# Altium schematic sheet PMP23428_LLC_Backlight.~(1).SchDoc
size 431 x 279 mm; Date: Not shown in title block; ApprovedBy: Not shown in title block; CheckedBy: Not shown in title block; Author: Not shown in title block; CompanyName: Not shown in title block; Engineer: Not shown in title block; Organization: Not shown in title block; Address1: Not shown in title block; Address2: Not shown in title block; Address3: Not shown in title block; Address4: Not shown in title block; DocumentNumber: 2; Revision: Use project parameter SCH_Rev; SheetNumber: 2; SheetTotal: 3; PageSetup: Record=PageOptions¦CenterHorizontal=True¦CenterVertical=True¦PrintScale=1.00¦XCorrection=1.00¦YCorrection=1.00¦PrintKind=0¦BorderSize=5000000¦LeftOffset=0¦BottomOffset=0¦Orientation=2¦PaperLength=1000¦PaperWidth=1000¦Scale=100¦PaperSource=15¦PrintQuality=600¦MediaType=1¦DitherType=10¦PaperKind=Letter¦PrintScaleMode=1
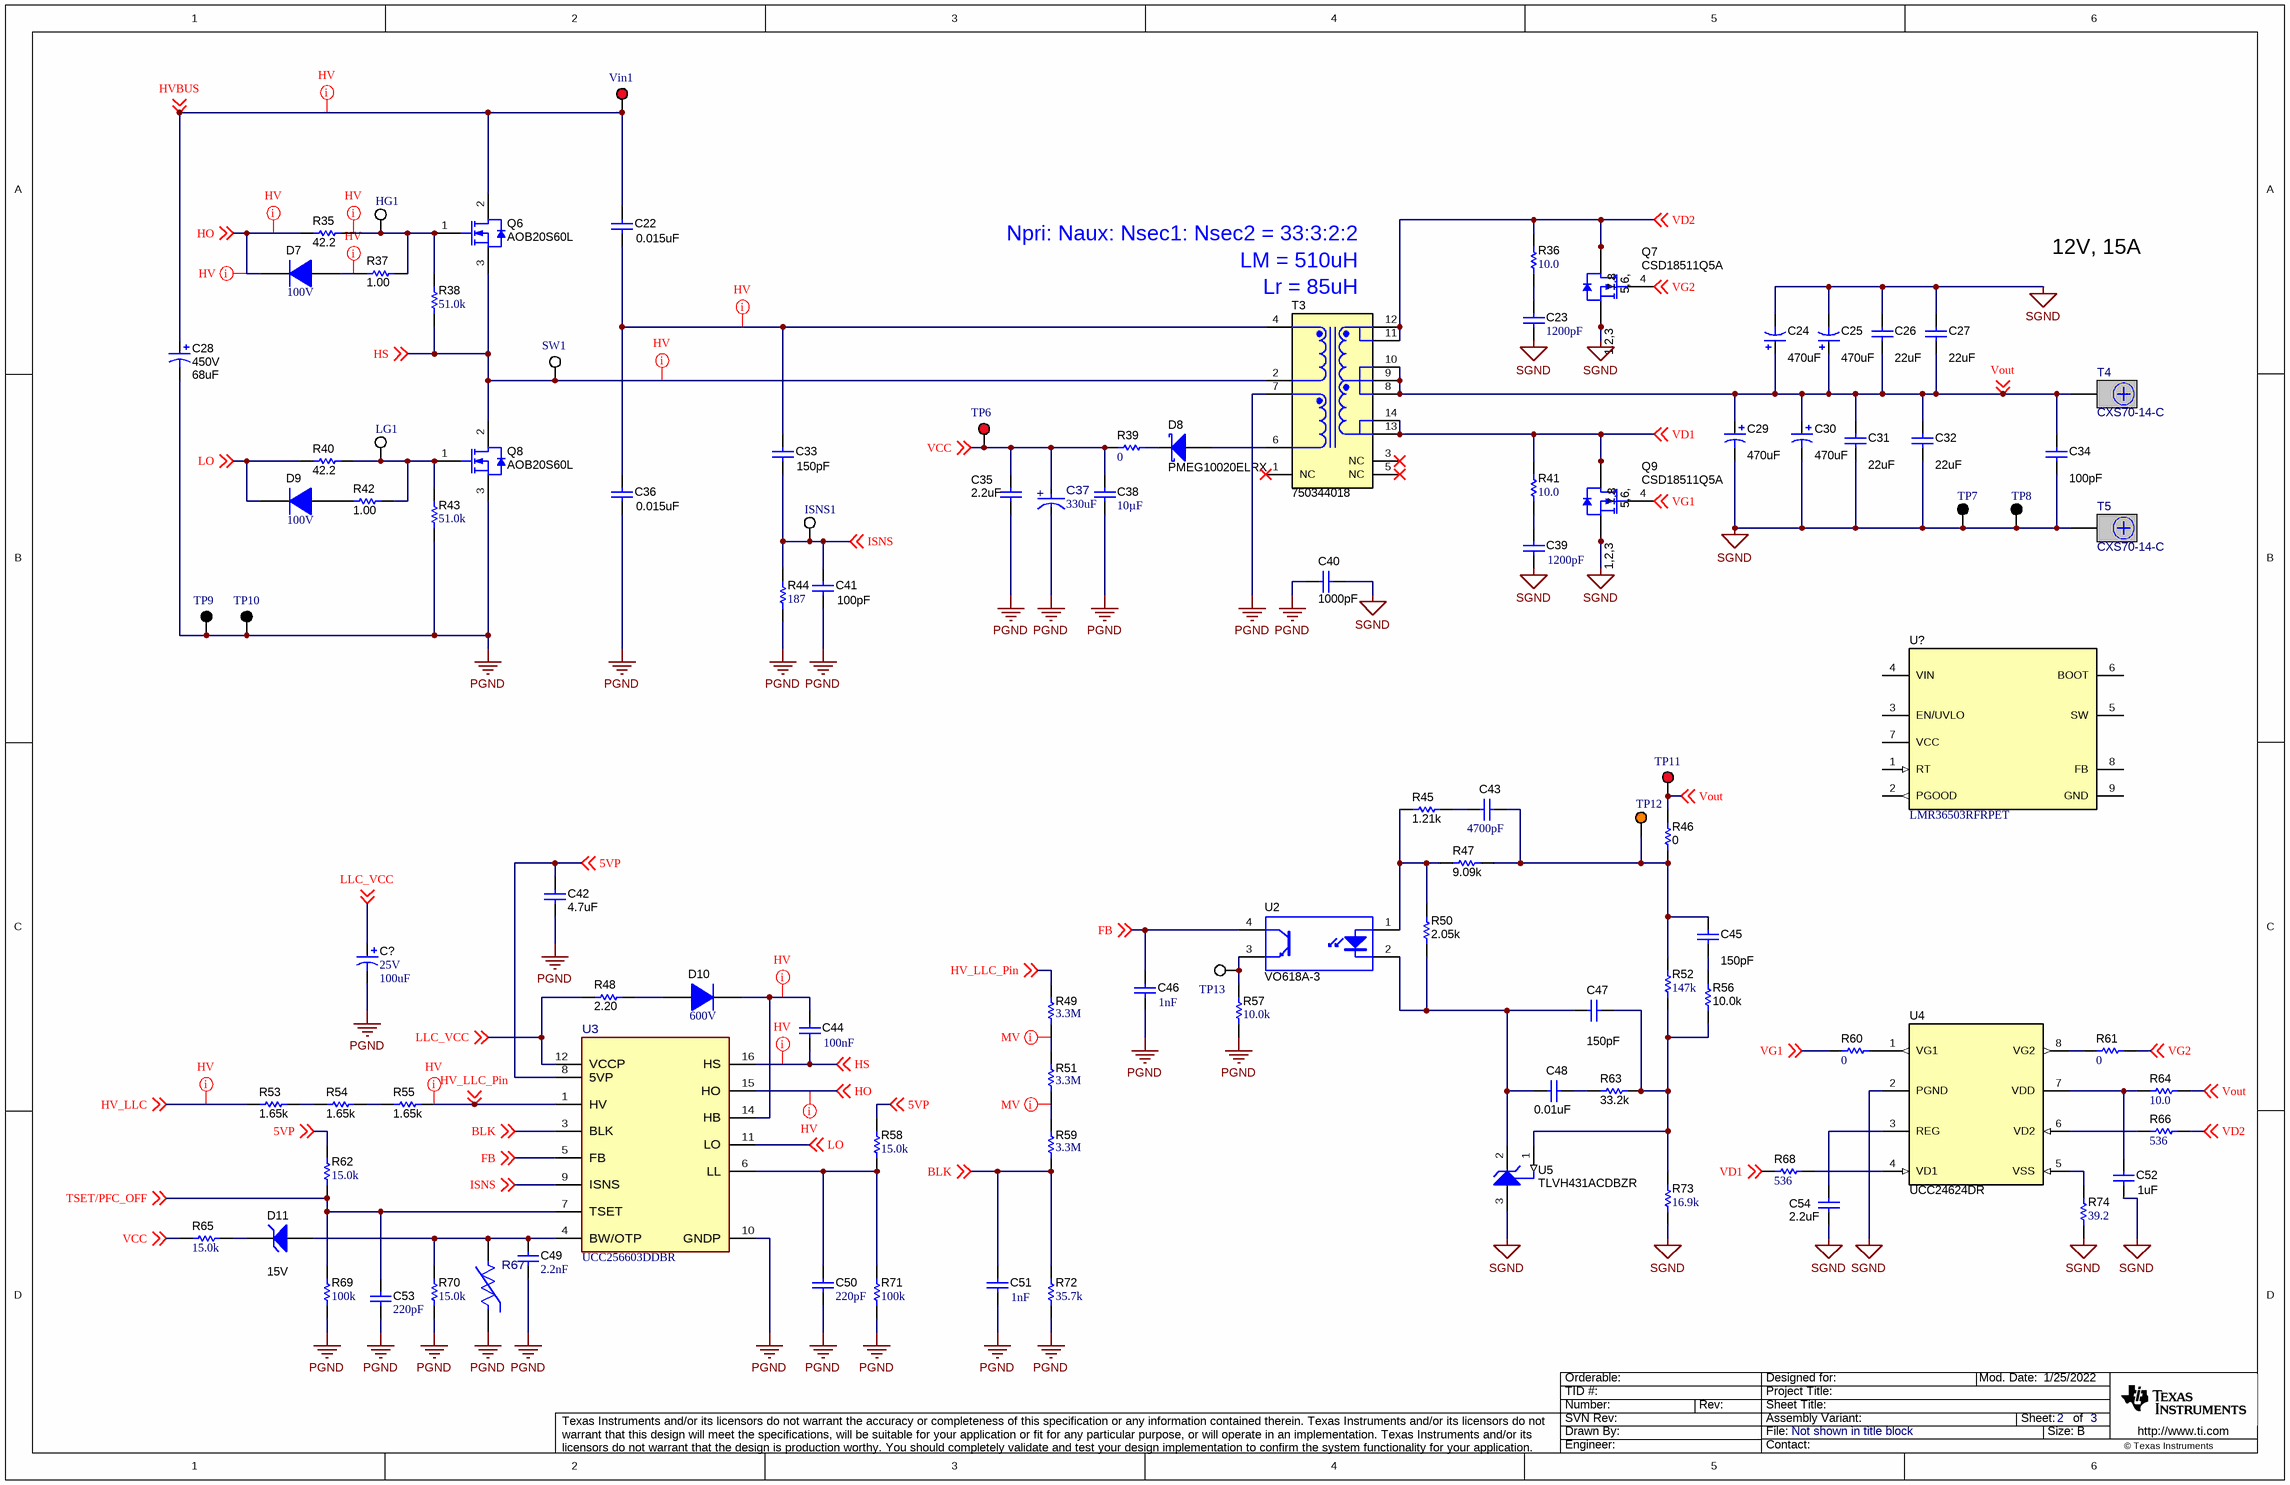
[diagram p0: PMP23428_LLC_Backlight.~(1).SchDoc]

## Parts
C22  ValueDisplayed: 0.015uF  [B32652_1800x700x1250]  (hidden comment: B32652A7153J000)
C23  ValueDisplayed: 1200pF  [0805L]  (hidden comment: GRM2165C2A122JA01D)
C24  ValueDisplayed: 470uF  [HW_1000x1600]  (hidden comment: UHW1V471MPD)
C25  ValueDisplayed: 470uF  [HW_1000x1600]  (hidden comment: UHW1V471MPD)
C26  ValueDisplayed: 22uF  [1206_190L]  (hidden comment: C3216X5R1E226M160AB)
C27  ValueDisplayed: 22uF  [1206_190L]  (hidden comment: C3216X5R1E226M160AB)
C28  VDC_V: 450V  ValueDisplayed: 68uF  [KXG_1800x3150]  (hidden comment: EKXG451ELL680MMN3S)
C29  ValueDisplayed: 470uF  [HW_1000x1600]  (hidden comment: UHW1V471MPD)
C30  ValueDisplayed: 470uF  [HW_1000x1600]  (hidden comment: UHW1V471MPD)
C31  ValueDisplayed: 22uF  [1206_190L]  (hidden comment: C3216X5R1E226M160AB)
C32  ValueDisplayed: 22uF  [1206_190L]  (hidden comment: C3216X5R1E226M160AB)
C33  ValueDisplayed: 150pF  [1206L]  (hidden comment: GRM31A5C2J151JW01D)
C34  ValueDisplayed: 100pF  [0603L]  (hidden comment: 06035A101FAT2A)
C35  ValueDisplayed: 2.2uF  [0805L]  (hidden comment: C2012X7R1V225K085AC)
C36  ValueDisplayed: 0.015uF  [B32652_1800x700x1250]  (hidden comment: B32652A7153J000)
C37  ValueDisplayed: 330uF  [FP-35ZL330MEFC10X16_RADIAL-MFG]  (hidden comment: 35ZL330MEFC10X16)
C38  ValueDisplayed: 10µF  [1206_180]  (hidden comment: C1206C106J3RACAUTO)
C39  ValueDisplayed: 1200pF  [0805L]  (hidden comment: GRM2165C2A122JA01D)
C40  ValueDisplayed: 1000pF  [CD45_700x600x1100]  (hidden comment: CD45-E2GA102M-NKA)
C41  ValueDisplayed: 100pF  [1206L]  (hidden comment: 12061A101JAT2A)
C42  ValueDisplayed: 4.7uF  [1206L]  (hidden comment: C3216X7R1E475K085AB)
C43  ValueDisplayed: 4700pF  [0603L]  (hidden comment: C0603C472J1GAC7867)
C44  Cap_F: 100nF  [1206_180L]  (hidden comment: GRM31C5C1E104JA01L)
C45  ValueDisplayed: 150pF  [0402L]  (hidden comment: 885012005062)
C46  Cap_F: 1nF  [1206L]  (hidden comment: 12061A102JAT2A)
C47  ValueDisplayed: 150pF  [0402L]  (hidden comment: 885012005062)
C48  ValueDisplayed: 0.01uF  [0603L]  (hidden comment: 06031C103JAT2A)
C49  Cap_F: 2.2nF  [0603]  (hidden comment: C0603X222K5RACTU)
C50  Cap_F: 220pF  [0603]  (hidden comment: C0603X221K5RACTU)
C51  Cap_F: 1nF  [0402L]  (hidden comment: 04025C102JAT2A)
C52  ValueDisplayed: 1uF  [0603L]  (hidden comment: GRM188R71C105KE15D)
C53  Cap_F: 220pF  [0603]  (hidden comment: C0603X221K5RACTU)
C54  ValueDisplayed: 2.2uF  [0805L]  (hidden comment: C2012X7R1V225K085AC)
C?  VDC_V: 25V  ValueDisplayed: 100uF  [SM_RADIAL_E]  (hidden comment: EEE-FK1E101P)
D7  Vr_V: 100V  [SOD-123]  (hidden comment: 1N4148W-7-F)
D8  PMEG10020ELRX  [SOD-123W]
D9  Vr_V: 100V  [SOD-123]  (hidden comment: 1N4148W-7-F)
D10  Vr_V: 600V  [SMAF]  (hidden comment: ES1JAF)
D11  value 15V  [SOD-123]  (hidden comment: DDZ15-7)
HG1  5012  [Keystone5012]  (value not drawn)
ISNS1  5012  [Keystone5012]  (value not drawn)
LG1  5012  [Keystone5012]  (value not drawn)
Q6  AOB20S60L  [DDPAK]
Q7  CSD18511Q5A  [DQJ0008A]
Q8  AOB20S60L  [DDPAK]
Q9  CSD18511Q5A  [DQJ0008A]
R35  ValueDisplayed: 42.2  [0603]  (hidden comment: RC0603FR-0742R2L)
R36  ValueDisplayed: 10.0  [1206L]  (hidden comment: RC1206FR-0710RL)
R37  ValueDisplayed: 1.00  [0603L]  (hidden comment: RC0603FR-071RL)
R38  ValueDisplayed: 51.0k  [0603L]  (hidden comment: RC0603FR-0751KL)
R39  ValueDisplayed: 0  [1206L]  (hidden comment: ERJ-8GEY0R00V)
R40  ValueDisplayed: 42.2  [0603L]  (hidden comment: RC0603FR-0742R2L)
R41  ValueDisplayed: 10.0  [1206L]  (hidden comment: RC1206FR-0710RL)
R42  ValueDisplayed: 1.00  [0603L]  (hidden comment: RC0603FR-071RL)
R43  ValueDisplayed: 51.0k  [0603L]  (hidden comment: RC0603FR-0751KL)
R44  ValueDisplayed: 187  [1206]  (hidden comment: RC1206FR-07187RL)
R45  ValueDisplayed: 1.21k  [0603L]  (hidden comment: RC0603FR-071K21L)
R46  ValueDisplayed: 0  [0402L]  (hidden comment: RC0402JR-070RL)
R47  ValueDisplayed: 9.09k  [0603L]  (hidden comment: RC0603FR-079K09L)
R48  ValueDisplayed: 2.20  [0603L]  (hidden comment: ERJ-3RQF2R2V)
R49  Res_ohm: 3.3M  [FP-KTR18EZPF3304_1206-MFG]  (hidden comment: KTR18EZPF3304)
R50  ValueDisplayed: 2.05k  [0603L]  (hidden comment: RC0603FR-072K05L)
R51  Res_ohm: 3.3M  [FP-KTR18EZPF3304_1206-MFG]  (hidden comment: KTR18EZPF3304)
R52  ValueDisplayed: 147k  [0603L]  (hidden comment: RC0603FR-07147KL)
R53  ValueDisplayed: 1.65k  [1206L]  (hidden comment: CRCW12061K65FKEA)
R54  ValueDisplayed: 1.65k  [1206L]  (hidden comment: CRCW12061K65FKEA)
R55  ValueDisplayed: 1.65k  [1206L]  (hidden comment: CRCW12061K65FKEA)
R56  ValueDisplayed: 10.0k  [0603L]  (hidden comment: ERJ-3EKF1002V)
R57  ValueDisplayed: 10.0k  [0402L]  (hidden comment: ERJ-2RKF1002X)
R58  ValueDisplayed: 15.0k  [0603]  (hidden comment: RT0603BRD0715KL)
R59  Res_ohm: 3.3M  [FP-KTR18EZPF3304_1206-MFG]  (hidden comment: KTR18EZPF3304)
R60  ValueDisplayed: 0  [0603L]  (hidden comment: RC0603JR-070RL)
R61  ValueDisplayed: 0  [0603L]  (hidden comment: RC0603JR-070RL)
R62  ValueDisplayed: 15.0k  [0603]  (hidden comment: RT0603BRD0715KL)
R63  ValueDisplayed: 33.2k  [0603L]  (hidden comment: RC0603FR-0733K2L)
R64  ValueDisplayed: 10.0  [0603L]  (hidden comment: RC0603FR-0710RL)
R65  ValueDisplayed: 15.0k  [0603]  (hidden comment: RG1608P-153-B-T5)
R66  ValueDisplayed: 536  [0603L]  (hidden comment: RT0603BRD07536RL)
R67  B57371V2474J060  [FP-B57371V2474J060_0603-MFG]  (value not drawn)
R68  ValueDisplayed: 536  [0603L]  (hidden comment: RT0603BRD07536RL)
R69  ValueDisplayed: 100k  [0603]  (hidden comment: RT0603BRD07100KL)
R70  ValueDisplayed: 15.0k  [0603]  (hidden comment: RG1608P-153-B-T5)
R71  ValueDisplayed: 100k  [0603]  (hidden comment: RT0603BRD07100KL)
R72  ValueDisplayed: 35.7k  [0603]  (hidden comment: RT0603BRD0735K7L)
R73  ValueDisplayed: 16.9k  [0603L]  (hidden comment: RC0603FR-0716K9L)
R74  ValueDisplayed: 39.2  [0603L]  (hidden comment: RC0603FR-0739R2L)
SW1  5012  [Keystone5012]  (value not drawn)
T3  750344018  [Wurth_750344018]
T4  CXS70-14-C  [Panduit_CXS70-14-C]
T5  CXS70-14-C  [Panduit_CXS70-14-C]
TP6  5010  [Keystone5010]  (value not drawn)
TP7  5011  [Keystone5011]  (value not drawn)
TP8  5011  [Keystone5011]  (value not drawn)
TP9  5011  [Keystone5011]  (value not drawn)
TP10  5011  [Keystone5011]  (value not drawn)
TP11  5010  [Keystone5010]  (value not drawn)
TP12  5013  [Keystone5013]  (value not drawn)
TP13  5012  [Keystone5012]  (value not drawn)
U2  VO618A-3  [DIP-4]
U3  UCC256603DDBR  [DDB0014A-MFG]
U4  UCC24624DR  [D0008A_N]
U5  TLVH431ACDBZR  [DBZ0003A_N]
U?  LMR36503RFRPET  [RPE0009A]
Vin1  5010  [Keystone5010]  (value not drawn)

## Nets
PGND: C28.2(-) C35.2 C36.2 C37.1(CATHODE) C38.2 C40.2 C41.2 C42.2 C46.2 C49.2 C50.2 C51.2 C53.2 C?.2(-) Q8.3(S) R43.1 R44.1 R57.1 R67.1 R69.1 R70.1 R71.1 R72.1 T3.7 TP9.1 TP10.1 U3.10(GNDP)
SGND: C23.2 C24.2(-) C25.2(-) C26.1 C27.1 C29.2(-) C30.2(-) C31.2 C32.2 C34.2 C39.2 C40.1 C52.2 C54.2 Q7.1(S) Q7.2(S) Q7.3(S) Q9.1(S) Q9.2(S) Q9.3(S) R73.1 R74.2 T5.1 TP7.1 TP8.1 U4.2(PGND) U5.3(ANODE)
5VP: C42.1 R58.2 R62.2 U3.8(5VP) ; off-sheet 5VP
BLK: C51.1 R59.1 R72.2 U3.3(BLK) ; off-sheet BLK
FB: C46.1 U2.4(C) U3.5(FB) ; off-sheet FB
HO: D7.1(K) R35.1 U3.15(HO) ; off-sheet HO
HS: C44.2 Q6.3(S) Q8.2(D) R38.1 SW1.1 T3.2 U3.16(HS) ; off-sheet HS
HV_LLC: R53.1 ; off-sheet HV_LLC
HV_LLC_Pin: R49.2 R55.2 U3.1(HV) ; off-sheet HV_LLC_Pin
HVBUS: C22.1 C28.1(+) Q6.2(D) Vin1.1 ; off-sheet HVBUS
ISNS: C33.2 C41.1 ISNS1.1 R44.2 U3.9(ISNS) ; off-sheet ISNS
LLC_VCC: C?.1(+) R48.1 U3.12(VCCP) ; off-sheet LLC_VCC
LO: D9.1(K) R40.1 U3.11(LO) ; off-sheet LO
TSET/PFC_OFF: C53.1 R62.1 R69.2 U3.7(TSET) ; off-sheet TSET/PFC_OFF
VCC: C35.1 C37.2(ANODE) C38.1 R39.1 R65.2 TP6.1 ; off-sheet VCC
VD1: Q9.5(D) Q9.6(D) Q9.7(D) Q9.8(D) Q9.9(D) R41.2 R68.2 T3.13 T3.14 ; off-sheet VD1
VD2: Q7.5(D) Q7.6(D) Q7.7(D) Q7.8(D) Q7.9(D) R36.2 R66.1 T3.11 T3.12 ; off-sheet VD2
VG1: Q9.4(G) R60.1 ; off-sheet VG1
VG2: Q7.4(G) R61.2 ; off-sheet VG2
Vout: C24.1(+) C25.1(+) C26.2 C27.2 C29.1(+) C30.1(+) C31.1 C32.1 C34.1 R46.2 R64.2 T3.8 T3.9 T3.10 T4.1 TP11.1 ; off-sheet Vout
NetC22_2: C22.2 C33.1 C36.1 T3.4
NetC23_1: C23.1 R36.1
NetC39_1: C39.1 R41.1
NetC43_1: C43.1 C45.1 R46.1 R47.2 R52.2 TP12.1
NetC43_2: C43.2 R45.2
NetC44_1: C44.1 D10.1(K) U3.14(HB)
NetC45_2: C45.2 R56.2
NetC47_1: C47.1 R52.1 R56.1 R63.1 R73.2 U5.1(REF)
NetC47_2: C47.2 C48.2 R50.1 U2.2(K) U5.2(CATHODE)
NetC48_1: C48.1 R63.2
NetC49_1: C49.1 D11.2(A) R67.2 R70.2 U3.4(BW/OTP)
NetC50_1: C50.1 R58.1 R71.2 U3.6(LL)
NetC52_1: C52.1 R64.1 U4.7(VDD)
NetC54_1: C54.1 U4.3(REG)
NetD7_2: D7.2(A) R37.1
NetD8_1: D8.1(K) R39.2
NetD8_2: D8.2(A) T3.6
NetD9_2: D9.2(A) R42.1
NetD10_2: D10.2(A) R48.2
NetD11_1: D11.1(K) R65.1
NetHG1_1: HG1.1 Q6.1(G) R35.2 R37.2 R38.2
NetLG1_1: LG1.1 Q8.1(G) R40.2 R42.2 R43.2
NetR45_1: R45.1 R47.1 R50.2 U2.1(A)
NetR49_1: R49.1 R51.2
NetR51_1: R51.1 R59.2
NetR53_2: R53.2 R54.1
NetR54_2: R54.2 R55.1
NetR57_2: R57.2 TP13.1 U2.3(E)
NetR60_2: R60.2 U4.1(VG1)
NetR61_1: R61.1 U4.8(VG2)
NetR66_2: R66.2 U4.6(VD2)
NetR68_1: R68.1 U4.4(VD1)
NetR74_1: R74.1 U4.5(VSS)

Not connected (* = marked no-connect by the designer): T3 1(NC)* 3(NC)* 5(NC)*; U? 1(RT) 2(PGOOD) 3(EN/UVLO) 4(VIN) 5(SW) 6(BOOT) 7(VCC) 8(FB) 9(GND)

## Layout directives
net class HV: HO, HS, HV_LLC, HV_LLC_Pin, HVBUS, NetC22_2, NetC44_1, NetD7_2, NetHG1_1
net class MV: NetR49_1, NetR51_1

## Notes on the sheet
- Npri: Naux: Nsec1: Nsec2 = 33:3:2:2
- LM = 510uH
- (near T3) Lr = 85uH
- 12V, 15A

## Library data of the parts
C22 C36 = CMP-0012346-3: CAP, Film, 0.015 uF, 1250 V, +/- 5%, AEC-Q200 Grade 3, TH; Manufacturer: TDK; TaMin_C: -55°C; Polarized: N; SizeAreaWB_mm2: 180; Value1: Unknown; TaMax_C: 100°C; SizeZ_mm: 12.5; SizeX_mm: 18; SizeY_mm: 7; Cap_Case: 18x7x12.5; Value2: 1250V; SizeArea_mm2: 126; CompType: Capacitor; AEC Qualified: Y; Cap_F: 15nF; VDC_V: 1.25kV; AEC Grade: 3; AEC Category: Q200
C23 C39 = CMP-0008098-2: CAP, CERM, 1200 pF, 100 V, +/- 5%, C0G/NP0, 0805; Manufacturer: MuRata; TaMin_C: -55°C; Polarized: N; SizeAreaWB_mm2: 6.75; Value1: Unknown; U/M: EA; Value: 1200pF; TaMax_C: 125°C; SizeZ_mm: 1.45; SizeX_mm: 2; SizeY_mm: 1.25; Cap_Case: 0805; Value2: 100V; SizeArea_mm2: 2.5; Cap_F: 1.2nF; AEC Category: Q200
C24 C25 C29 C30 = CMP-0010541-2: CAP, AL, 470 uF, 35 V, +/- 20%, 0.03 ohm, TH; Manufacturer: Nichicon; TaMin_C: -40°C; ESR_ohm: 0.03; Polarized: Y; SizeAreaWB_mm2: 144; U/M: EA; Value: 470uF; TaMax_C: 105°C; SizeZ_mm: 17.5; SizeX_mm: 10; Cap_Case: 10x16mm; Value2: 35V; SizeArea_mm2: 100; CompType: Capacitor; AEC Qualified: N; Cap_F: 470µF; IRMS_A: 2A; AEC Category: Q200
C26 C27 C31 C32 = CMP-0008654-2: CAP, CERM, 22 uF, 25 V, +/- 20%, X5R, 1206_190; Manufacturer: TDK; TaMin_C: -55°C; Polarized: N; SizeAreaWB_mm2: 10.92; Value1: Unknown; U/M: EA; Value: 22uF; TaMax_C: 85°C; SizeZ_mm: 1.9; SizeX_mm: 3.2; SizeY_mm: 1.6; Cap_Case: 1206; Value2: 25V; SizeArea_mm2: 5.12; CompType: Capacitor; Cap_F: 22µF; AEC Category: Q200
C28 = CMP-0010043-2: CAP, AL, 68 uF, 450 V, +/- 20%, TH; Manufacturer: Chemi-Con; TaMin_C: -25°C; Polarized: Y; SizeAreaWB_mm2: 400; Value1: Unknown; U/M: EA; Value: 68uF; TaMax_C: 105°C; SizeZ_mm: 33; SizeX_mm: 18; Cap_Case: 18x31.5mm; SizeArea_mm2: 324; CompType: Capacitor; Cap_F: 68µF; IRMS_A: 6.3dA; AEC Category: Q200
C33 = CMP-0008885-2: CAP, CERM, 150 pF, 630 V, +/- 5%, C0G/NP0, 1206; Manufacturer: MuRata; TaMin_C: -55°C; Polarized: N; SizeAreaWB_mm2: 10.92; Value1: Unknown; U/M: EA; Value: 150pF; TaMax_C: 125°C; SizeZ_mm: 1.35; SizeX_mm: 3.2; SizeY_mm: 1.6; Cap_Case: 1206; Value2: 630V; SizeArea_mm2: 5.12; CompType: Capacitor; AEC Category: Q200
C34 = CMP-0006762-4: CAP, CERM, 100 pF, 50 V, +/- 1%, C0G/NP0, 0603; Manufacturer: AVX; TaMin_C: -55°C; Polarized: N; SizeAreaWB_mm2: 4.68; Value1: Unknown; U/M: EA; TaMax_C: 125°C; SizeZ_mm: 1; SizeX_mm: 1.6; SizeY_mm: 0.8; Cap_Case: 0603; Value2: 50V; SizeArea_mm2: 1.28; CompType: Capacitor; Value: 100pF; AEC Category: Q200
C35 C54 = CMP-0007883-2: CAP, CERM, 2.2 uF, 35 V, +/- 10%, X7R, 0805; Manufacturer: TDK; TaMin_C: -55°C; Polarized: N; SizeAreaWB_mm2: 6.75; Value1: Unknown; U/M: EA; Value: 2.2uF; TaMax_C: 125°C; SizeZ_mm: 1.45; SizeX_mm: 2; SizeY_mm: 1.25; Cap_Case: 0805; Value2: 35V; SizeArea_mm2: 2.5; CompType: Capacitor; Cap_F: 2.2µF; AEC Category: Q200
C37 = CMP-0098283-1: Cap Aluminum Lytic 330uF 35V 20% (10 X 16mm) Radial 5mm 1430mA 4000h 105C Bulk; Manufacturer: Rubycon; AEC Qualified: No; Cap_F: 330µF; IRMS_A: 1.43A; SizeZ_mm: 17.5mm; Dissipation Factor: 12%; Leakage Current: 115.5uA; Life: 4000Hours; Value: 330µF
C38 = CMP-0081062-1: CAP, CERM, 10 µF, 25 V,+/- 5%, X7R, AEC-Q200 Grade 1, 1206; Manufacturer: Kemet; TaMin_C: -55°C; Polarized: N; SizeAreaWB_mm2: 10.92; U/M: EA; Value: 10uF; TaMax_C: 125°C; SizeZ_mm: 1.8; SizeX_mm: 3.2; SizeY_mm: 1.6; Value2: 25V; SizeArea_mm2: 5.12; AEC Qualified: Y; AEC Grade: 1; AEC Category: Q200
C40 = CMP-0009595-2: CAP, CERM, 1000 pF,  V, +/- 20%, E, D7xT6mm; Manufacturer: TDK; TaMin_C: -25°C; Polarized: N; SizeAreaWB_mm2: 101.2; Value1: Unknown; U/M: EA; Value: 1000pF; TaMax_C: 125°C; SizeZ_mm: 11; SizeX_mm: 10.65; SizeY_mm: 6; Cap_Case: 7x6x11mm; SizeArea_mm2: 63.9; Cap_F: 1nF; AEC Category: Q200
C41 = CMP-0008462-2: CAP, CERM, 100 pF, 100 V, +/- 5%, C0G/NP0, 1206; Manufacturer: AVX; TaMin_C: -55°C; ESR_ohm: 7.01d; Polarized: N; SizeAreaWB_mm2: 10.92; Value1: 0.701 ohm; U/M: EA; Value: 100pF; TaMax_C: 125°C; SizeZ_mm: 1.35; SizeX_mm: 3.2; SizeY_mm: 1.6; Cap_Case: 1206; Value2: 100V; SizeArea_mm2: 5.12; CompType: Capacitor; AEC Category: Q200
C42 = CMP-0008693-2: CAP, CERM, 4.7 uF, 25 V, +/- 10%, X7R, 1206; Manufacturer: TDK; TaMin_C: -55°C; Polarized: N; SizeAreaWB_mm2: 10.92; Value1: Unknown; U/M: EA; Value: 4.7uF; TaMax_C: 125°C; SizeZ_mm: 1.35; SizeX_mm: 3.2; SizeY_mm: 1.6; Cap_Case: 1206; Value2: 25V; SizeArea_mm2: 5.12; CompType: Capacitor; Cap_F: 4.7µF; AEC Category: Q200
C43 = CMP-0006941-4: CAP, CERM, 4700 pF, 100 V, +/- 5%, C0G/NP0, 0603; Manufacturer: Kemet; TaMin_C: -55°C; Polarized: N; SizeAreaWB_mm2: 4.68; Value1: Unknown; U/M: EA; Value: 4700pF; TaMax_C: 125°C; SizeZ_mm: 1; SizeX_mm: 1.6; SizeY_mm: 0.8; Cap_Case: 0603; Value2: 100V; SizeArea_mm2: 1.28; Cap_F: 4.7nF; AEC Category: Q200
C44 = CMP-0064950-2: CAP, CERM, 0.1 uF, 25 V,+/- 5%, C0G/NP0, 1206; Manufacturer: MuRata; TaMin_C: -55°C; Polarized: N; SizeAreaWB_mm2: 10.92; Value1: Unknown; U/M: EA; Value: 0.1uF; TaMax_C: 125°C; SizeZ_mm: 1.8; SizeX_mm: 3.2; SizeY_mm: 1.6; Cap_Case: 1206; Value2: 25V; SizeArea_mm2: 5.12; AEC Category: Q200
C45 C47 = CMP-0064913-2: CAP, CERM, 150 pF, 50 V,+/- 5%, C0G/NP0, 0402; Manufacturer: Wurth Elektronik; TaMin_C: -55°C; Polarized: N; SizeAreaWB_mm2: 3; Value1: Unknown; U/M: EA; Value: 150pF; TaMax_C: 125°C; SizeZ_mm: 0.6; SizeX_mm: 1; SizeY_mm: 0.5; Cap_Case: 0402; Value2: 50V; CompType: Capacitor; AEC Category: Q200
C46 = CMP-0008465-2: CAP, CERM, 1000 pF, 100 V, +/- 5%, C0G/NP0, 1206; Manufacturer: AVX; TaMin_C: -55°C; ESR_ohm: 2.38d; Polarized: N; SizeAreaWB_mm2: 10.92; Value1: 0.238 ohm; U/M: EA; Value: 1000pF; TaMax_C: 125°C; SizeZ_mm: 1.35; SizeX_mm: 3.2; SizeY_mm: 1.6; Cap_Case: 1206; Value2: 100V; SizeArea_mm2: 5.12; AEC Category: Q200
C48 = CMP-0006726-4: CAP, CERM, 0.01 uF, 100 V, +/- 5%, X7R, 0603; Manufacturer: AVX; TaMin_C: -55°C; ESR_ohm: 0.098; Polarized: N; SizeAreaWB_mm2: 4.68; Value1: 0.098 ohm; U/M: EA; Value: 0.01uF; TaMax_C: 125°C; SizeZ_mm: 1; SizeX_mm: 1.6; SizeY_mm: 0.8; Cap_Case: 0603; Value2: 100V; SizeArea_mm2: 1.28; Cap_F: 10nF; AEC Category: Q200
C49 = CMP-0006983-4: CAP, CERM, 2200 pF, 50 V, +/- 10%, X7R, 0603; Manufacturer: Kemet; TaMin_C: -55°C; Polarized: N; SizeAreaWB_mm2: 4.68; Value1: Unknown; U/M: EA; Value: 2200pF; TaMax_C: 125°C; SizeZ_mm: 1; SizeX_mm: 1.6; SizeY_mm: 0.8; Value2: 50V; SizeArea_mm2: 1.28; AEC Category: Q200
C50 C53 = CMP-0006982-4: CAP, CERM, 220 pF, 50 V, +/- 10%, X7R, 0603; Manufacturer: Kemet; TaMin_C: -55°C; Polarized: N; SizeAreaWB_mm2: 4.68; Value1: Unknown; U/M: EA; Value: 220pF; TaMax_C: 125°C; SizeZ_mm: 1; SizeX_mm: 1.6; SizeY_mm: 0.8; Value2: 50V; SizeArea_mm2: 1.28; AEC Category: Q200
C51 = CMP-0861060-1: CAP, CERM, 1000 pF, 50 V,+/- 5%, X7R, 0402; Manufacturer: AVX; Value2: 50V; SizeY_mm: 0.5; AEC Category: Q200; Polarized: N; Green_Lifecycle: Active; SizeAreaWB_mm2: 3; ValueDisplayed: 1000pF; Cap_Case: 0402; Value: 1000pF; TaMin_C: -55°C; U/M: EA; Green_REACh: Passed; SizeZ_mm: 0.6; SizeX_mm: 1; TaMax_C: 125°C
C52 = CMP-0007380-4: CAP, CERM, 1 uF, 16 V, +/- 10%, X7R, 0603; Manufacturer: MuRata; TaMin_C: -55°C; Polarized: N; SizeAreaWB_mm2: 4.68; Value1: Unknown; U/M: EA; Value: 1uF; TaMax_C: 125°C; SizeZ_mm: 1; SizeX_mm: 1.6; SizeY_mm: 0.8; Cap_Case: 0603; Value2: 16V; SizeArea_mm2: 1.28; CompType: Capacitor; Cap_F: 1µF; AEC Category: Q200
C? = CMP-0010710-1: CAP, AL, 100 uF, 25 V, +/- 20%, 0.26 ohm, AEC-Q200 Grade 2, SMD; Manufacturer: Panasonic; TaMin_C: -55°C; ESR_ohm: 2.6d; Polarized: Y; SizeAreaWB_mm2: 118.45; U/M: EA; Value: 100uF; TaMax_C: 105°C; SizeZ_mm: 6.2; SizeX_mm: 9.5; SizeY_mm: 8.3; Cap_Case: E; SizeArea_mm2: 78.85; CompType: Capacitor; Cap_F: 100µF; IRMS_A: 3dA; AEC Grade: 2; AEC Category: Q200
D7 D9 = CMP-0029001-2: Diode, Ultrafast, 100 V, 0.15 A, SOD-123; Manufacturer: Diodes Inc.; Io_A: 150mA; Green_Lifecycle: Active; SizeAreaWB_mm2: 13.095; Green_REACh: Passed; Value1: 0.15A; TJmax_C: 150°C; Value: 100V; SizeZ_mm: 1.35; SizeX_mm: 3.85; SizeY_mm: 1.7; Vf_V: 1.25V; SizeArea_mm2: 6.545; AEC Category: Q101
D8 = CMP-0028977-2: Diode, Schottky, 100 V, 2 A, AEC-Q101, SOD-123W; Manufacturer: Nexperia; Io_A: 2A; SizeAreaWB_mm2: 12.15; Vr_V: 100V; TJmax_C: 175°C; Value: 100V; SizeZ_mm: 1; SizeX_mm: 3.5; SizeY_mm: 1.7; Vf_V: 830mV; Value2: 0.83V; SizeArea_mm2: 5.95; AEC Qualified: Y; AEC Category: Q101
D10 = CMP-0029162-2: Diode, Ultrafast, 600 V, 1 A, AEC-Q101, SMAF; Manufacturer: Fairchild Semiconductor; Io_A: 1A; Green_Lifecycle: Not Set; SizeAreaWB_mm2: 19.95; Green_REACh: Incomplete; TJmax_C: 150°C; Value: 600V; SizeZ_mm: 1; SizeX_mm: 4.7; SizeY_mm: 2.5; Vf_V: 1.7V; SizeArea_mm2: 11.75; AEC Qualified: Y; AEC Category: Q101
D11 = CMP-0085135-1: Diode, Zener, 15 V, 500 mW, SOD-123; Manufacturer: Diodes Inc.; SizeAreaWB_mm2: 13.095; SizeArea_mm2: 6.545; SizeY_mm: 1.7; AEC Qualified: N; SizeZ_mm: 1.35; Value1: 0.5W; SizeX_mm: 3.85; Power_W: 500mW; RJA_CperW: 425; AEC Category: Q101
HG1 ISNS1 LG1 SW1 TP13 = CMP-0055149-2: Test Point, Multipurpose, White, TH; Manufacturer: Keystone Electronics; CNHeader: FALSE; Green_Lifecycle: Active; Green_REACh: Passed; ContactFinish: Silver; CT: TRUE
Q6 Q8 = CMP-0001135-4: MOSFET, N-CH, 600 V, 20 A, DDPAK; Alternate Manufacturer: None; Manufacturer: AOS; SizeZ_mm: 4.445; ChType: N; Value2: 19.8 nC; VdsMax_V: 600V; SizeX_mm: 15.245; SizeAreaWB_mm2: 209.6992; SizeY_mm: 10.16; Vgs_V: 30V; QgTyp_nC: 19.8; Value: 600V; SizeArea_mm2: 154.8892; AEC Category: Q101; IdsMax_A: 20A; ChMode: Enhancement
Q7 Q9 = CMP-0000711-1: MOSFET, N-CH, 40 V, 100 A, DQJ0008A (VSONP-8); Alternate Manufacturer: None; Manufacturer: Texas Instruments; SizeZ_mm: 1.1; ChType: N; Value2: 63 nC; Value1: 0.003; VdsMax_V: 40V; SizeX_mm: 6; SizeY_mm: 4.9; Vgs_V: 20V; Value: 40V; Rdson45_ohm: 3.5m; SizeArea_mm2: 29.4; AEC Category: Q101; IdsMax_A: 100A; SizeAreaWB_mm2: 55.2; U/M: EA; QgTyp_nC: 63
R35 R40 = CMP-0023107-5: RES, 42.2, 1%, 0.1 W, 0603; Manufacturer: Yageo; Power_W: 100mW; TempCo: 100 ppm/C; Value_Code: 42R2; Value: 42.2; EIA_Code: E96; SizeX_mm: 1.6; SizeY_mm: 0.8; SizeZ_mm: 1; Value2: 0.1W; SizeArea_mm2: 1.28; CompType: Resistor; AEC Qualified: N; VDC_V: 75V; AEC Category: Q200; SizeAreaWB_mm2: 4.68
R36 R41 = CMP-0017851-2: RES, 10.0, 1%, 0.25 W, 1206; Manufacturer: Yageo America; Power_W: 250mW; TempCo: 200 ppm/C; Value_Code: 10R0; U/M: EA; Value: 10.0; EIA_Code: E96; Res_ohm: 10; SizeX_mm: 3.2; SizeY_mm: 1.6; SizeZ_mm: 1.35; Value2: 0.25W; SizeArea_mm2: 5.12; VDC_V: 200V; AEC Category: Q200
R37 R42 = CMP-0022900-4: RES, 1.00, 1%, 0.1 W, 0603; Manufacturer: Yageo; Power_W: 100mW; TempCo: 200 ppm/C; Value_Code: 1R00; Value: 1.00; EIA_Code: E96; Res_ohm: 1; SizeX_mm: 1.6; SizeY_mm: 0.8; Value2: 0.1W; SizeArea_mm2: 1.28; CompType: Resistor; AEC Qualified: N; VDC_V: 75V; AEC Category: Q200; SizeAreaWB_mm2: 4.68
R38 R43 = CMP-0023167-5: RES, 51.0 k, 1%, 0.1 W, 0603; Manufacturer: Yageo; Power_W: 100mW; TempCo: 100 ppm/C; Value_Code: 51k0; Value: 51.0k; Res_ohm: 51k; SizeX_mm: 1.6; SizeY_mm: 0.8; SizeZ_mm: 1; Value2: 0.1W; SizeArea_mm2: 1.28; AEC Qualified: N; VDC_V: 75V; AEC Category: Q200; SizeAreaWB_mm2: 4.68
R39 = CMP-0018748-3: RES, 0, 5%, 0.25 W, AEC-Q200 Grade 0, 1206; Manufacturer: Panasonic; Power_W: 250mW; TempCo: 600 ppm/C; Value_Code: 0000; Value: 0; EIA_Code: E24; SizeX_mm: 3.2; SizeY_mm: 1.6; SizeZ_mm: 1.35; Value2: 0.25W; SizeArea_mm2: 5.12; AEC Qualified: Y; VDC_V: 200V; AEC Category: Q200; SizeAreaWB_mm2: 10.92
R44 = CMP-0017949-2: RES, 187, 1%, 0.25 W, 1206; Manufacturer: Yageo America; Power_W: 250mW; TempCo: 100 ppm/C; Value_Code: 187R; U/M: EA; Value: 187; EIA_Code: E96; SizeX_mm: 3.2; SizeY_mm: 1.6; SizeZ_mm: 1.35; Value2: 0.25W; SizeArea_mm2: 5.12; VDC_V: 200V; AEC Category: Q200
R45 = CMP-0022871-5: RES, 1.21 k, 1%, 0.1 W, 0603; Manufacturer: Yageo; Power_W: 100mW; TempCo: 100 ppm/C; Value_Code: 1k21; Value: 1.21k; EIA_Code: E96; SizeX_mm: 1.6; SizeY_mm: 0.8; SizeZ_mm: 1; Value2: 0.1W; SizeArea_mm2: 1.28; AEC Qualified: N; VDC_V: 75V; AEC Category: Q200; SizeAreaWB_mm2: 4.68
R46 = CMP-0027004-2: RES, 0, 5%, 0.063 W, 0402; Manufacturer: Yageo America; Power_W: 63mW; TempCo: 200 ppm/C; Value_Code: 0000; U/M: EA; Value: 0; EIA_Code: E24; SizeX_mm: 1; SizeY_mm: 0.5; SizeZ_mm: 0.6; Value2: 0.063W; CompType: Resistor; VDC_V: 50V; AEC Category: Q200
R47 = CMP-0023332-5: RES, 9.09 k, 1%, 0.1 W, 0603; Manufacturer: Yageo; Power_W: 100mW; TempCo: 100 ppm/C; Value_Code: 9k09; Value: 9.09k; EIA_Code: E96; SizeX_mm: 1.6; SizeY_mm: 0.8; SizeZ_mm: 1; Value2: 0.1W; SizeArea_mm2: 1.28; AEC Qualified: N; VDC_V: 75V; AEC Category: Q200; SizeAreaWB_mm2: 4.68
R48 = CMP-0022711-2: RES, 2.20, 1%, 0.1 W, 0603; Manufacturer: Panasonic; Power_W: 100mW; TempCo: 200 ppm/C; Value_Code: 2R20; U/M: EA; Value: 2.20; Res_ohm: 2.2; SizeX_mm: 1.6; SizeY_mm: 0.8; SizeZ_mm: 1; Value2: 0.1W; SizeArea_mm2: 1.28; CompType: Resistor; AEC Category: Q200
R49 R51 R59 = CMP-0087456-2: 3.3 MOhms ±1% 0.25W, 1/4W Chip Resistor 1206 (3216 Metric) Automotive AEC-Q200, High Voltage Thick Film; Manufacturer: Rohm Semiconductor; AEC Qualified: Yes; Power_W: 250mW; SizeZ_mm: 0.65mm; AEC Grade: Grade 0; TempCo: 100ppm/°C; VDC_V: 500V
R50 = CMP-0022981-5: RES, 2.05 k, 1%, 0.1 W, 0603; Manufacturer: Yageo; Power_W: 100mW; TempCo: 100 ppm/C; Value_Code: 2k05; Value: 2.05k; EIA_Code: E96; SizeX_mm: 1.6; SizeY_mm: 0.8; SizeZ_mm: 1; Value2: 0.1W; SizeArea_mm2: 1.28; AEC Qualified: N; VDC_V: 75V; AEC Category: Q200; SizeAreaWB_mm2: 4.68
R52 = CMP-0022800-4: RES, 147 k, 1%, 0.1 W, 0603; Manufacturer: Yageo; Power_W: 100mW; TempCo: 100 ppm/C; Value: 147k; EIA_Code: E96; SizeX_mm: 1.6; SizeY_mm: 0.8; SizeZ_mm: 1; Value2: 0.1W; SizeArea_mm2: 1.28; AEC Qualified: N; VDC_V: 75V; AEC Category: Q200; SizeAreaWB_mm2: 4.68
R53-R55 = CMP-0016708-3: RES, 1.65 k, 1%, 0.25 W, AEC-Q200 Grade 0, 1206; Manufacturer: Vishay-Dale; Power_W: 250mW; TempCo: 100 ppm/C; Value_Code: 1k65; Value: 1.65k; EIA_Code: E96; SizeX_mm: 3.2; SizeY_mm: 1.6; SizeZ_mm: 1.35; Value2: 0.25W; SizeArea_mm2: 5.12; CompType: Resistor; AEC Qualified: Y; VDC_V: 200V; AEC Category: Q200; AEC Grade: 0
R56 = CMP-0022684-3: RES, 10.0 k, 1%, 0.1 W, 0603; Manufacturer: Panasonic; Power_W: 100mW; TempCo: 100 ppm/C; Value_Code: 10k0; U/M: EA; Value: 10.0k; EIA_Code: E96; Res_ohm: 10k; SizeX_mm: 1.6; SizeY_mm: 0.8; SizeZ_mm: 1; Value2: 0.1W; SizeArea_mm2: 1.28; CompType: Resistor; VDC_V: 75V; AEC Category: Q200
R57 = CMP-0026658-1: RES, 10.0 k, 1%, 0.1 W, 0402; Manufacturer: Panasonic; Power_W: 100mW; TempCo: 100 ppm/C; Value_Code: 10k0; U/M: EA; Value: 10.0k; EIA_Code: E96; Res_ohm: 10k; SizeX_mm: 1; SizeY_mm: 0.5; SizeZ_mm: 0.6; Value2: 0.1W; VDC_V: 50V; AEC Category: Q200
R58 R62 = CMP-0023780-3: RES, 15.0 k, 0.1%, 0.1 W, 0603; Manufacturer: Yageo America; Power_W: 100mW; TempCo: 25 ppm/C; Value_Code: 15k0; U/M: EA; Value: 15.0k; EIA_Code: E192; Res_ohm: 15k; SizeX_mm: 1.6; SizeY_mm: 0.8; SizeZ_mm: 1; Value2: 0.1W; SizeArea_mm2: 1.28; VDC_V: 75V; AEC Category: Q200
R60 R61 = CMP-0025885-5: RES, 0, 5%, 0.1 W, 0603; Manufacturer: Yageo; Power_W: 100mW; TempCo: 200 ppm/C; Value_Code: 0000; Value: 0; EIA_Code: E24; SizeX_mm: 1.6; SizeZ_mm: 1; Value2: 0.1W; SizeArea_mm2: 1.28; AEC Qualified: N; VDC_V: 75V; AEC Category: Q200; SizeY_mm: 0.8; SizeAreaWB_mm2: 4.68
R63 = CMP-0023036-5: RES, 33.2 k, 1%, 0.1 W, 0603; Manufacturer: Yageo; Power_W: 100mW; TempCo: 100 ppm/C; Value_Code: 33k2; Value: 33.2k; EIA_Code: E96; SizeX_mm: 1.6; SizeY_mm: 0.8; SizeZ_mm: 1; Value2: 0.1W; SizeArea_mm2: 1.28; AEC Qualified: N; VDC_V: 75V; AEC Category: Q200; SizeAreaWB_mm2: 4.68
R64 = CMP-0022751-4: RES, 10.0, 1%, 0.1 W, 0603; Manufacturer: Yageo; Power_W: 100mW; TempCo: 100 ppm/C; Value_Code: 10R0; Value: 10.0; EIA_Code: E96; Res_ohm: 10; SizeX_mm: 1.6; SizeY_mm: 0.8; SizeZ_mm: 1; Value2: 0.1W; SizeArea_mm2: 1.28; AEC Qualified: N; VDC_V: 75V; AEC Category: Q200; SizeAreaWB_mm2: 4.68
R65 R70 = CMP-0023441-3: RES, 15.0 k, 0.1%, 0.1 W, 0603; Manufacturer: Susumu Co Ltd; Power_W: 100mW; TempCo: 25 ppm/C; Value_Code: 15k0; U/M: EA; Value: 15.0k; EIA_Code: E192; Res_ohm: 15k; SizeX_mm: 1.6; SizeY_mm: 0.8; SizeZ_mm: 1; Value2: 0.1W; SizeArea_mm2: 1.28; VDC_V: 75V; AEC Category: Q200
R66 R68 = CMP-0024324-2: RES, 536, 0.1%, 0.1 W, 0603; Manufacturer: Yageo America; Power_W: 100mW; TempCo: 25 ppm/C; Value_Code: 536R; U/M: EA; Value: 536; EIA_Code: E192; SizeX_mm: 1.6; SizeY_mm: 0.8; SizeZ_mm: 1; Value2: 0.1W; SizeArea_mm2: 1.28; VDC_V: 75V; AEC Category: Q200
R67 = CMP-0096703-1: NTC Thermistor 470k 0603 (1608 Metric); Manufacturer: TDK; AEC Qualified: No; Res_ohm: 470kΩ; Power_W: 180mW; B 25 50: 4386K; B 25 100: 4480K; SizeZ_mm: 0.9mm; B 25 85: 4455K; B Tolerance: 3%; Tolerance_%: 5%
R69 R71 = CMP-0023630-3: RES, 100 k, 0.1%, 0.1 W, 0603; Manufacturer: Yageo America; Power_W: 100mW; TempCo: 25 ppm/C; U/M: EA; Value: 100k; EIA_Code: E192; SizeX_mm: 1.6; SizeY_mm: 0.8; SizeZ_mm: 1; Value2: 0.1W; SizeArea_mm2: 1.28; VDC_V: 75V; AEC Category: Q200
R72 = CMP-0024147-3: RES, 35.7 k, 0.1%, 0.1 W, 0603; Manufacturer: Yageo America; Power_W: 100mW; TempCo: 25 ppm/C; Value_Code: 35k7; U/M: EA; Value: 35.7k; EIA_Code: E192; SizeX_mm: 1.6; SizeY_mm: 0.8; SizeZ_mm: 1; Value2: 0.1W; SizeArea_mm2: 1.28; VDC_V: 75V; AEC Category: Q200
R73 = CMP-0022830-5: RES, 16.9 k, 1%, 0.1 W, 0603; Manufacturer: Yageo; Power_W: 100mW; TempCo: 100 ppm/C; Value_Code: 16k9; Value: 16.9k; EIA_Code: E96; SizeX_mm: 1.6; SizeY_mm: 0.8; SizeZ_mm: 1; Value2: 0.1W; SizeArea_mm2: 1.28; AEC Qualified: N; VDC_V: 75V; AEC Category: Q200; SizeAreaWB_mm2: 4.68
R74 = CMP-0023074-4: RES, 39.2, 1%, 0.1 W, 0603; Manufacturer: Yageo; Power_W: 100mW; TempCo: 100 ppm/C; Value_Code: 39R2; Value: 39.2; EIA_Code: E96; SizeX_mm: 1.6; SizeY_mm: 0.8; SizeZ_mm: 1; Value2: 0.1W; SizeArea_mm2: 1.28; AEC Qualified: N; VDC_V: 75V; AEC Category: Q200; SizeAreaWB_mm2: 4.68
T3 = CMP-0081993-1: Transformer, 510 uH, TH; Manufacturer: Wurth Elektronik; SizeAreaWB_mm2: 1732.5; SizeArea_mm2: 1569.5; AEC Qualified: N; Ns2toNp: 0.06; Lp: 510; AEC Category: Q200; Value: 510uH; SizeZ_mm: 26.5; Ind_H: 510µH; SizeY_mm: 43; LeakageInd_H: 85µH; SizeX_mm: 36.5
T4 T5 = CMP-0075010-2: Terminal 70A Lug; Manufacturer: Panduit; CNHeader: False; Green_Lifecycle: Not Set; Green_REACh: Incomplete; CompType: Screw Terminal
TP6 TP11 Vin1 = CMP-0055147-2: Test Point, Multipurpose, Red, TH; Manufacturer: Keystone Electronics; CNHeader: FALSE; Green_Lifecycle: Active; Green_REACh: Passed; ContactFinish: Silver; CT: TRUE
TP7 TP8 = CMP-0055148-2: Test Point, Multipurpose, Black, TH; Manufacturer: Keystone Electronics; CNHeader: FALSE; ContactFinish: Silver; Green_REACh: Passed; Green_Lifecycle: Active; CT: TRUE
TP9 TP10 = CMP-0055148-2: Test Point, Multipurpose, Black, TH; Manufacturer: Keystone Electronics; CNHeader: FALSE; Green_Lifecycle: Active; Green_REACh: Passed; ContactFinish: Silver; CT: TRUE
TP12 = CMP-0055150-2: Test Point, Multipurpose, Orange, TH; Manufacturer: Keystone Electronics; CNHeader: FALSE; Green_Lifecycle: Active; Green_REACh: Passed; ContactFinish: Silver; CT: TRUE
U2 = CMP-0083653-1: Optocoupler, 5.3 kV, 100-200% CTR, SMT; Manufacturer: Vishay-Semiconductor; CTR (Max): 200%; SizeAreaWB_mm2: 71.064; CTR (Min): 100%; SizeZ_mm: 5; SizeX_mm: 8.8; SizeY_mm: 4.58; SizeArea_mm2: 40.304; Voltage_Isolation_Vrms: 5.3kV
U3 = CMP-0095299-1: 750kHz Wide VIN/VOUT Range LLC Controller Optimized for Light Load Efficiency; Manufacturer: Texas Instruments; Number Of Outputs: 2; TaMax_C: +125°C; Output Type: Other; TJmax_C: +150°C; AEC Qualified: No; Standoff Height: 0.1mm; TaMin_C: -40°C; SizeZ_mm: 1.75mm; Switching Frequency: 30-750kHz; Max Supply Voltage: 18.5V
U4 = CMP-0079610-1: High Performance Synchronous Rectifier Driver for LLC Resonant Converter, D0008A (SOIC-8); Alternate Manufacturer: Texas Instruments; SizeAreaWB_mm2: 56.58; SizeZ_mm: 1.75; SizeX_mm: 4.9; SizeY_mm: 6.2; SizeArea_mm2: 30.38; CompType: IC; AEC Qualified: N; AEC Category: Q200
U5 = CMP-0033066-1: Low-Voltage Adjustable Precision Shunt Regulator, 129 ppm / degC, 80 mA, 0 to 70 degC, 3-pin SOT-23 (DBZ), Green (RoHS & no Sb/Br); Manufacturer: Texas Instruments; Min Iz for Regulation(uA): 80; VO Adj(Max)(V): 18; VO Adj(Min)(V): 1.24; Rating: Catalog; SubFamily: Shunt Voltage Reference; Temp Coeff(Max)(ppm/ degree C): 129
U? = CMP-0750087-1: LMR36503/06-Q1 Wide Input 60-V Synchronous, DC-DC Buck Converter, RPE0009A (VQFN-9); Alternate PartNumber: LMR36503RFRPER; Alternate Manufacturer: Texas Instruments; SizeAreaWB_mm2: 9; SizeY_mm: 2; SizeArea_mm2: 4; SizeZ_mm: 1; CompType: IC; AEC Qualified: N; AEC Category: Q200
